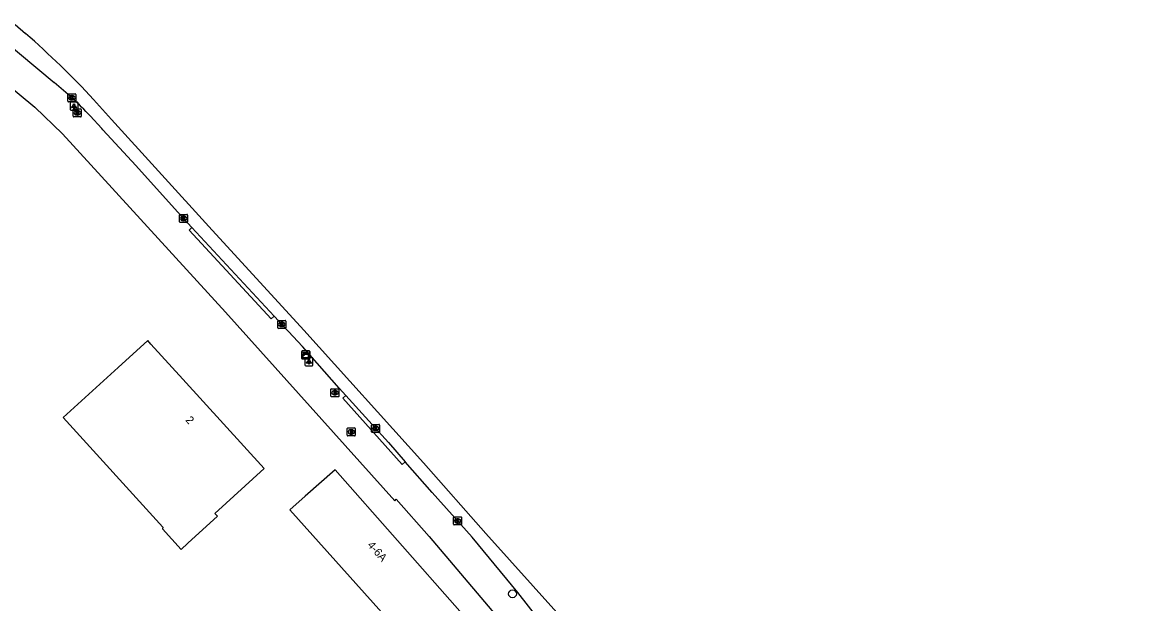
# Model space of a CAD drawing. Extents: x 161354 to 161876, y 382161 to 382804.
# Drawn here: x 161566.5 to 161706, y 382658.6 to 382731.2 of the extents above; entities that cross this region are included whole.
import ezdxf

# ---------------------------------------------------------------- set-up
doc = ezdxf.new("R2010")
doc.units = 0
for name, color, linetype in [('IMGEO_Boom', 7, 'Continuous'), ('IMGEO_Brandkraan', 7, 'Continuous'), ('IMGEO_Fietspad_gesloten', 7, 'Continuous'), ('IMGEO_Kast', 7, 'Continuous'), ('IMGEO_Kolk', 7, 'Continuous'), ('IMGEO_Lichtpunt', 7, 'Continuous'), ('IMGEO_Pand', 7, 'Continuous'), ('IMGEO_Pand_nummerreeks', 7, 'Continuous'), ('IMGEO_Rijbaan_lokaal_gesloten', 7, 'Continuous'), ('IMGEO_Rioolput', 7, 'Continuous'), ('IMGEO_Voetpad_open', 7, 'Continuous')]:
    doc.layers.add(name, color=color, linetype=linetype)

msp = doc.modelspace()

# ---------------------------------------------------------------- linework, layer by layer
at = {"layer": 'IMGEO_Boom'}
msp.add_circle((161627.74, 382659.79), 0.489, dxfattribs=at)
at = {"layer": 'IMGEO_Brandkraan'}
for p, q in [((161607.09, 382679.6), (161607.09, 382680.45)), ((161607.16, 382680.52), (161608.01, 382680.52)), ((161608.01, 382679.52), (161607.16, 382679.52)), ((161607.6, 382679.74), (161607.57, 382679.74)), ((161607.58, 382680.3), (161607.6, 382680.3)), ((161608.09, 382680.45), (161608.09, 382679.6))]:
    msp.add_line(p, q, dxfattribs=at)
for points in [[(161607.09, 382679.6), (161607.09, 382680.45)], [(161607.16, 382680.52), (161608.01, 382680.52)], [(161608.01, 382679.52), (161607.16, 382679.52)], [(161607.43, 382680.22), (161607.43, 382679.82), (161607.65, 382679.82)], [(161607.67, 382680.22), (161607.43, 382680.22)], [(161607.61, 382680.14), (161607.56, 382680.14), (161607.56, 382680.07)], [(161607.56, 382680.07), (161607.61, 382680.07)], [(161607.62, 382679.99), (161607.56, 382679.99), (161607.56, 382679.91)], [(161607.56, 382679.91), (161607.62, 382679.91)], [(161608.09, 382680.45), (161608.09, 382679.6)]]:
    msp.add_lwpolyline(points, dxfattribs=at)
for centre, radius, start, end in [((161607.16, 382680.45), 0.0765, 91.552, 178.448), ((161607.16, 382680.45), 0.0765, 91.552, 178.448), ((161607.16, 382679.6), 0.0765, 181.552, 268.448), ((161607.16, 382679.6), 0.0765, 181.552, 268.448), ((161607.61, 382680.1), 0.0379, 267.8285, 90.9355), ((161607.62, 382679.95), 0.0404, 269.8759, 90.5077), ((161607.65, 382680.07), 0.251, 268.6676, 293.5347), ((161607.67, 382680.08), 0.145, 59.4692, 91.5367), ((161607.7, 382680.13), 0.0922, 285.5137, 58.1501), ((161607.7, 382679.93), 0.105, 301.3115, 78.989), ((161608.01, 382680.45), 0.0765, 1.552, 88.448), ((161608.01, 382680.45), 0.0765, 1.552, 88.448), ((161608.01, 382679.6), 0.0765, 271.552, 358.448), ((161608.01, 382679.6), 0.0765, 271.552, 358.448)]:
    msp.add_arc(centre, radius, start, end, dxfattribs=at)
for centre, major_axis, ratio, start_param, end_param in [((161607.57, 382680.02), (-0.387, 0.002), 0.722429, 4.712389, 7.853982), ((161607.6, 382680.02), (-0.39, 0.002), 0.717154, 1.570796, 4.712389)]:
    msp.add_ellipse(centre, major_axis=major_axis, ratio=ratio, start_param=start_param, end_param=end_param, dxfattribs=at)
at = {"layer": 'IMGEO_Fietspad_gesloten'}
for points in [[(161570.46, 382723.64), (161563.83, 382729.15)], [(161587.67, 382705.55), (161586.62, 382706.68), (161580.68, 382713.28), (161576.55, 382717.76), (161576.42, 382717.91), (161574.95, 382719.49)], [(161587.67, 382705.55), (161597.96, 382694.49)], [(161606.91, 382684.56), (161606.09, 382685.47), (161601.5, 382690.67), (161597.96, 382694.49)], [(161606.91, 382684.56), (161612.23, 382678.69), (161614.34, 382676.28)], [(161631.21, 382656.39), (161631.08, 382656.55), (161628.4, 382659.96), (161626.26, 382662.59), (161622.7, 382666.88), (161617.71, 382672.44), (161614.34, 382676.28)]]:
    msp.add_lwpolyline(points, dxfattribs=at)
msp.add_arc((161543.58, 382690.11), 42.98, 43.1263, 51.2866, dxfattribs=at)
at = {"layer": 'IMGEO_Kast'}
for p, q in [((161601.4, 382689.21), (161601.4, 382690.05)), ((161601.4, 382690.05), (161601.4, 382689.21)), ((161601.47, 382690.13), (161602.31, 382690.13)), ((161602.31, 382690.13), (161601.47, 382690.13)), ((161602.32, 382689.14), (161601.48, 382689.14)), ((161601.48, 382689.14), (161602.32, 382689.14)), ((161602.4, 382690.06), (161602.4, 382689.22)), ((161602.4, 382689.22), (161602.4, 382690.06))]:
    msp.add_line(p, q, dxfattribs=at)
for points in [[(161601.59, 382689.93), (161602.19, 382689.93), (161602.19, 382689.84), (161601.59, 382689.84), (161601.59, 382689.93)], [(161601.59, 382689.75), (161602.19, 382689.75), (161602.19, 382689.26), (161601.59, 382689.26), (161601.59, 382689.75)]]:
    msp.add_lwpolyline(points, dxfattribs=at)
msp.add_circle((161601.68, 382689.6), 0.0377, dxfattribs=at)
for centre, start, end in [((161601.48, 382690.06), 92.4484, 184.2845), ((161601.48, 382690.06), 92.4484, 184.2845), ((161601.48, 382689.21), 182.4484, 274.2845), ((161601.48, 382689.21), 182.4484, 274.2845), ((161602.32, 382690.06), 2.4484, 94.2845), ((161602.32, 382690.06), 2.4484, 94.2845), ((161602.32, 382689.21), 272.4484, 4.2845), ((161602.32, 382689.21), 272.4484, 4.2845)]:
    msp.add_arc(centre, 0.0779, start, end, dxfattribs=at)
at = {"layer": 'IMGEO_Kolk'}
for p, q in [((161572.17, 382721.32), (161572.17, 382722.17)), ((161572.24, 382722.25), (161573.09, 382722.25)), ((161573.09, 382721.25), (161572.24, 382721.25)), ((161572.68, 382721.47), (161572.65, 382721.47)), ((161572.66, 382722.03), (161572.68, 382722.03)), ((161573.17, 382722.17), (161573.17, 382721.32)), ((161586.13, 382706.26), (161586.13, 382707.11)), ((161586.2, 382707.18), (161587.05, 382707.18)), ((161587.05, 382706.18), (161586.2, 382706.18)), ((161586.61, 382706.96), (161586.64, 382706.96)), ((161586.64, 382706.4), (161586.61, 382706.4)), ((161587.13, 382707.11), (161587.13, 382706.26)), ((161598.41, 382693.02), (161598.41, 382693.87)), ((161598.48, 382693.95), (161599.33, 382693.95)), ((161598.89, 382693.73), (161598.92, 382693.73)), ((161599.41, 382693.87), (161599.41, 382693.02)), ((161599.33, 382692.95), (161598.48, 382692.95)), ((161598.92, 382693.17), (161598.89, 382693.17)), ((161610.12, 382680.03), (161610.12, 382680.88)), ((161610.2, 382680.96), (161611.05, 382680.96)), ((161611.13, 382680.88), (161611.13, 382680.03)), ((161611.05, 382679.96), (161610.2, 382679.96)), ((161610.61, 382680.74), (161610.64, 382680.74)), ((161610.63, 382680.18), (161610.61, 382680.18)), ((161620.38, 382668.48), (161620.38, 382669.33)), ((161620.46, 382669.4), (161621.31, 382669.4)), ((161621.31, 382668.4), (161620.46, 382668.4)), ((161620.87, 382669.18), (161620.9, 382669.18)), ((161620.89, 382668.62), (161620.87, 382668.62)), ((161621.38, 382669.33), (161621.38, 382668.48))]:
    msp.add_line(p, q, dxfattribs=at)
for points in [[(161572.17, 382721.32), (161572.17, 382722.17)], [(161572.24, 382722.25), (161573.09, 382722.25)], [(161573.09, 382721.25), (161572.24, 382721.25)], [(161572.49, 382721.95), (161572.61, 382721.95), (161572.61, 382721.8), (161572.74, 382721.95), (161572.91, 382721.95), (161572.76, 382721.8), (161572.91, 382721.55), (161572.76, 382721.55), (161572.68, 382721.71), (161572.61, 382721.64), (161572.61, 382721.55), (161572.49, 382721.55), (161572.49, 382721.95)], [(161573.17, 382722.17), (161573.17, 382721.32)], [(161586.13, 382706.26), (161586.13, 382707.11)], [(161586.2, 382707.18), (161587.05, 382707.18)], [(161587.05, 382706.18), (161586.2, 382706.18)], [(161586.45, 382706.88), (161586.57, 382706.88), (161586.57, 382706.73), (161586.7, 382706.88), (161586.86, 382706.88), (161586.72, 382706.73), (161586.87, 382706.48), (161586.72, 382706.48), (161586.63, 382706.65), (161586.57, 382706.58), (161586.57, 382706.48), (161586.45, 382706.48), (161586.45, 382706.88)], [(161587.13, 382707.11), (161587.13, 382706.26)], [(161598.41, 382693.02), (161598.41, 382693.87)], [(161598.48, 382693.95), (161599.33, 382693.95)], [(161598.73, 382693.65), (161598.85, 382693.65), (161598.85, 382693.5), (161598.98, 382693.65), (161599.14, 382693.65), (161599, 382693.5), (161599.15, 382693.25), (161599, 382693.25), (161598.91, 382693.41), (161598.85, 382693.34), (161598.85, 382693.25), (161598.73, 382693.25), (161598.73, 382693.65)], [(161599.41, 382693.87), (161599.41, 382693.02)], [(161599.33, 382692.95), (161598.48, 382692.95)], [(161610.12, 382680.03), (161610.12, 382680.88)], [(161610.2, 382680.96), (161611.05, 382680.96)], [(161611.13, 382680.88), (161611.13, 382680.03)], [(161611.05, 382679.96), (161610.2, 382679.96)], [(161610.44, 382680.66), (161610.57, 382680.66), (161610.57, 382680.5), (161610.7, 382680.66), (161610.86, 382680.66), (161610.72, 382680.51), (161610.87, 382680.26), (161610.72, 382680.26), (161610.63, 382680.42), (161610.57, 382680.35), (161610.57, 382680.26), (161610.44, 382680.26), (161610.44, 382680.66)], [(161620.38, 382668.48), (161620.38, 382669.33)], [(161620.46, 382669.4), (161621.31, 382669.4)], [(161621.31, 382668.4), (161620.46, 382668.4)], [(161620.7, 382669.1), (161620.83, 382669.1), (161620.83, 382668.95), (161620.96, 382669.1), (161621.12, 382669.1), (161620.97, 382668.95), (161621.13, 382668.7), (161620.97, 382668.7), (161620.89, 382668.87), (161620.83, 382668.8), (161620.83, 382668.7), (161620.7, 382668.7), (161620.7, 382669.1)], [(161621.38, 382669.33), (161621.38, 382668.48)]]:
    msp.add_lwpolyline(points, dxfattribs=at)
for centre, start, end in [((161572.24, 382722.17), 91.552, 178.448), ((161572.24, 382722.17), 91.552, 178.448), ((161572.24, 382721.32), 181.552, 268.448), ((161572.24, 382721.32), 181.552, 268.448), ((161573.09, 382722.17), 1.552, 88.448), ((161573.09, 382722.17), 1.552, 88.448), ((161573.09, 382721.32), 271.552, 358.448), ((161573.09, 382721.32), 271.552, 358.448), ((161586.2, 382707.11), 91.552, 178.448), ((161586.2, 382707.11), 91.552, 178.448), ((161586.2, 382706.26), 181.552, 268.448), ((161586.2, 382706.26), 181.552, 268.448), ((161587.05, 382707.11), 1.552, 88.448), ((161587.05, 382707.11), 1.552, 88.448), ((161587.05, 382706.26), 271.552, 358.448), ((161587.05, 382706.26), 271.552, 358.448), ((161598.48, 382693.87), 91.552, 178.448), ((161598.48, 382693.87), 91.552, 178.448), ((161599.33, 382693.87), 1.552, 88.448), ((161599.33, 382693.87), 1.552, 88.448), ((161598.48, 382693.02), 181.552, 268.448), ((161598.48, 382693.02), 181.552, 268.448), ((161599.33, 382693.02), 271.552, 358.448), ((161599.33, 382693.02), 271.552, 358.448), ((161610.2, 382680.88), 91.552, 178.448), ((161610.2, 382680.88), 91.552, 178.448), ((161611.05, 382680.88), 1.552, 88.448), ((161611.05, 382680.88), 1.552, 88.448), ((161610.2, 382680.03), 181.552, 268.448), ((161610.2, 382680.03), 181.552, 268.448), ((161611.05, 382680.03), 271.552, 358.448), ((161611.05, 382680.03), 271.552, 358.448), ((161620.46, 382669.33), 91.552, 178.448), ((161620.46, 382669.33), 91.552, 178.448), ((161620.46, 382668.48), 181.552, 268.448), ((161620.46, 382668.48), 181.552, 268.448), ((161621.31, 382669.33), 1.552, 88.448), ((161621.31, 382669.33), 1.552, 88.448), ((161621.31, 382668.48), 271.552, 358.448), ((161621.31, 382668.48), 271.552, 358.448)]:
    msp.add_arc(centre, 0.0765, start, end, dxfattribs=at)
for centre, major_axis, ratio, start_param, end_param in [((161572.65, 382721.75), (-0.387, 0.002), 0.722429, 4.712389, 7.853982), ((161572.68, 382721.75), (-0.39, 0.002), 0.717154, 1.570796, 4.712389), ((161586.61, 382706.68), (-0.387, 0.002), 0.722429, 4.712389, 7.853982), ((161586.64, 382706.68), (-0.39, 0.002), 0.717154, 1.570796, 4.712389), ((161598.89, 382693.45), (-0.387, 0.002), 0.722429, 4.712389, 7.853982), ((161598.92, 382693.45), (-0.39, 0.002), 0.717154, 1.570796, 4.712389), ((161610.61, 382680.46), (-0.387, 0.002), 0.722429, 4.712389, 7.853982), ((161610.64, 382680.46), (-0.39, 0.002), 0.717154, 1.570796, 4.712389), ((161620.87, 382668.9), (-0.387, 0.002), 0.722429, 4.712389, 7.853982), ((161620.89, 382668.9), (-0.39, 0.002), 0.717154, 1.570796, 4.712389)]:
    msp.add_ellipse(centre, major_axis=major_axis, ratio=ratio, start_param=start_param, end_param=end_param, dxfattribs=at)
at = {"layer": 'IMGEO_Lichtpunt'}
for p, q in [((161573.35, 382721.21), (161572.54, 382721.21)), ((161573.35, 382721.21), (161572.54, 382721.21)), ((161572.44, 382721.12), (161572.44, 382720.31)), ((161572.44, 382721.12), (161572.44, 382720.31)), ((161572.54, 382720.22), (161573.35, 382720.22)), ((161572.54, 382720.22), (161573.35, 382720.22)), ((161573.44, 382720.31), (161573.44, 382721.12)), ((161573.44, 382720.31), (161573.44, 382721.12)), ((161601.8, 382689.19), (161601.8, 382688.38)), ((161601.8, 382689.19), (161601.8, 382688.38)), ((161602.7, 382689.29), (161601.89, 382689.29)), ((161602.7, 382689.29), (161601.89, 382689.29)), ((161602.79, 382688.38), (161602.79, 382689.19)), ((161602.79, 382688.38), (161602.79, 382689.19)), ((161601.89, 382688.29), (161602.7, 382688.29)), ((161601.89, 382688.29), (161602.7, 382688.29))]:
    msp.add_line(p, q, dxfattribs=at)
for points in [[(161572.82, 382720.78), (161572.86, 382720.75), (161572.67, 382720.49), (161572.63, 382720.52), (161572.82, 382720.78)], [(161572.92, 382720.73), (161572.97, 382720.73), (161572.97, 382720.41), (161572.92, 382720.41), (161572.92, 382720.73)], [(161573.03, 382720.75), (161573.07, 382720.78), (161573.26, 382720.52), (161573.22, 382720.49), (161573.03, 382720.75)], [(161602.17, 382688.85), (161602.21, 382688.83), (161602.02, 382688.56), (161601.98, 382688.59), (161602.17, 382688.85)], [(161602.27, 382688.81), (161602.32, 382688.81), (161602.32, 382688.48), (161602.27, 382688.48), (161602.27, 382688.81)], [(161602.38, 382688.83), (161602.42, 382688.85), (161602.61, 382688.59), (161602.57, 382688.56), (161602.38, 382688.83)]]:
    msp.add_lwpolyline(points, dxfattribs=at)
for centre in [(161572.94, 382720.92), (161602.3, 382688.99)]:
    msp.add_circle(centre, 0.0994, dxfattribs=at)
for centre, start, end in [((161572.54, 382721.12), 90, 180), ((161572.54, 382721.12), 90, 180), ((161573.35, 382721.12), 0, 90), ((161573.35, 382721.12), 0, 90), ((161572.54, 382720.31), 180, 270), ((161572.54, 382720.31), 180, 270), ((161573.35, 382720.31), 270, 0), ((161573.35, 382720.31), 270, 360), ((161601.89, 382689.19), 90, 180), ((161601.89, 382689.19), 90, 180), ((161602.7, 382689.19), 0, 90), ((161602.7, 382689.19), 0, 90), ((161601.89, 382688.38), 180, 270), ((161601.89, 382688.38), 180, 270), ((161602.7, 382688.38), 270, 0), ((161602.7, 382688.38), 270, 360)]:
    msp.add_arc(centre, 0.0946, start, end, dxfattribs=at)
at = {"layer": 'IMGEO_Pand'}
for points in [[(161587.17, 382666.11), (161590.86, 382669.48), (161590.53, 382669.84), (161596.7, 382675.46), (161586.54, 382686.62), (161582.55, 382691), (161582.15, 382691.45), (161578.45, 382688.08), (161571.58, 382681.82), (161584.05, 382668.13), (161583.98, 382667.91), (161586.32, 382665.34), (161587.17, 382666.11)], [(161608.6, 382646.59), (161611.37, 382642.43), (161621.26, 382649.02), (161617.61, 382654.49), (161621.16, 382657.62), (161605.59, 382675.28), (161601.84, 382671.98), (161599.92, 382670.28), (161613.9, 382654.66), (161606.56, 382649.65), (161608.6, 382646.59)]]:
    msp.add_lwpolyline(points, dxfattribs=at)
at = {"layer": 'IMGEO_Rijbaan_lokaal_gesloten'}
for points in [[(161565.59, 382730.91), (161566.88, 382729.79)], [(161575.38, 382721.55), (161577.62, 382719.05), (161589.77, 382705.69), (161601.67, 382692.72), (161616.61, 382676.14), (161624.39, 382667.35), (161636.24, 382654.18), (161636.58, 382653.81), (161653.9, 382634.56), (161673.99, 382613.71), (161706.01, 382577.79), (161705.64, 382575.65)]]:
    msp.add_lwpolyline(points, dxfattribs=at)
msp.add_arc((161490.37, 382642.4), 116.15, 42.9532, 48.7982, dxfattribs=at)
at = {"layer": 'IMGEO_Rioolput'}
for p, q in [((161572.84, 382719.45), (161572.84, 382720.3)), ((161572.91, 382720.38), (161573.77, 382720.38)), ((161573.33, 382720.16), (161573.35, 382720.16)), ((161573.84, 382720.3), (161573.84, 382719.45)), ((161573.77, 382719.38), (161572.91, 382719.38)), ((161573.35, 382719.6), (161573.33, 382719.6)), ((161605.05, 382684.5), (161605.05, 382685.35)), ((161605.13, 382685.42), (161605.98, 382685.42)), ((161605.54, 382685.2), (161605.56, 382685.2)), ((161606.05, 382685.35), (161606.05, 382684.5)), ((161605.98, 382684.42), (161605.13, 382684.42)), ((161605.56, 382684.64), (161605.54, 382684.64))]:
    msp.add_line(p, q, dxfattribs=at)
for points in [[(161572.84, 382719.45), (161572.84, 382720.3)], [(161572.91, 382720.38), (161573.77, 382720.38)], [(161573.43, 382720.07), (161573.18, 382720.08), (161573.18, 382719.68)], [(161573.18, 382719.68), (161573.3, 382719.68), (161573.3, 382719.84), (161573.31, 382719.84)], [(161573.36, 382720), (161573.3, 382720), (161573.3, 382719.91)], [(161573.3, 382719.91), (161573.35, 382719.91)], [(161573.84, 382720.3), (161573.84, 382719.45)], [(161573.77, 382719.38), (161572.91, 382719.38)], [(161573.36, 382719.81), (161573.43, 382719.68), (161573.57, 382719.68), (161573.5, 382719.8)], [(161605.05, 382684.5), (161605.05, 382685.35)], [(161605.13, 382685.42), (161605.98, 382685.42)], [(161605.64, 382685.12), (161605.39, 382685.12), (161605.39, 382684.72)], [(161605.57, 382685.04), (161605.51, 382685.04), (161605.51, 382684.96)], [(161605.51, 382684.96), (161605.56, 382684.96)], [(161606.05, 382685.35), (161606.05, 382684.5)], [(161605.98, 382684.42), (161605.13, 382684.42)], [(161605.39, 382684.72), (161605.51, 382684.72), (161605.51, 382684.89), (161605.52, 382684.89)], [(161605.57, 382684.86), (161605.64, 382684.72), (161605.78, 382684.72), (161605.72, 382684.85)]]:
    msp.add_lwpolyline(points, dxfattribs=at)
for centre, radius, start, end in [((161572.92, 382720.3), 0.0765, 91.552, 178.448), ((161572.92, 382720.3), 0.0765, 91.552, 178.448), ((161573.31, 382719.79), 0.0533, 26.0293, 88.6989), ((161573.34, 382720.1), 0.19, 274.7715, 282.9687), ((161573.36, 382719.9), 0.0964, 77.0061, 93.1865), ((161573.38, 382719.96), 0.0378, 276.6634, 79.6772), ((161573.43, 382719.97), 0.109, 350.3612, 89.416), ((161573.43, 382719.96), 0.112, 277.5842, 350.9817), ((161573.41, 382719.75), 0.108, 29.5134, 73.7905), ((161573.76, 382720.3), 0.0765, 1.552, 88.448), ((161573.76, 382720.3), 0.0765, 1.552, 88.448), ((161572.92, 382719.45), 0.0765, 181.552, 268.448), ((161572.92, 382719.45), 0.0765, 181.552, 268.448), ((161573.76, 382719.45), 0.0765, 271.552, 358.448), ((161573.76, 382719.45), 0.0765, 271.552, 358.448), ((161605.13, 382685.35), 0.0765, 91.552, 178.448), ((161605.13, 382685.35), 0.0765, 91.552, 178.448), ((161605.55, 382685.15), 0.19, 274.7715, 282.9687), ((161605.57, 382684.95), 0.0964, 77.0061, 93.1865), ((161605.59, 382685), 0.0378, 276.6634, 79.6772), ((161605.64, 382685.01), 0.109, 350.3612, 89.416), ((161605.64, 382685.01), 0.112, 277.5842, 350.9817), ((161605.98, 382685.35), 0.0765, 1.552, 88.448), ((161605.98, 382685.35), 0.0765, 1.552, 88.448), ((161605.13, 382684.5), 0.0765, 181.552, 268.448), ((161605.13, 382684.5), 0.0765, 181.552, 268.448), ((161605.52, 382684.83), 0.0533, 26.0293, 88.6989), ((161605.62, 382684.8), 0.108, 29.5134, 73.7905), ((161605.98, 382684.5), 0.0765, 271.552, 358.448), ((161605.98, 382684.5), 0.0765, 271.552, 358.448)]:
    msp.add_arc(centre, radius, start, end, dxfattribs=at)
for centre, major_axis, ratio, start_param, end_param in [((161573.33, 382719.88), (-0.387, 0.002), 0.722429, 4.712389, 7.853982), ((161573.35, 382719.88), (-0.39, 0.002), 0.717154, 1.570796, 4.712389), ((161605.54, 382684.92), (-0.387, 0.002), 0.722429, 4.712389, 7.853982), ((161605.56, 382684.92), (-0.39, 0.002), 0.717154, 1.570796, 4.712389)]:
    msp.add_ellipse(centre, major_axis=major_axis, ratio=ratio, start_param=start_param, end_param=end_param, dxfattribs=at)
at = {"layer": 'IMGEO_Voetpad_open'}
for points in [[(161555.24, 382731.18), (161568.03, 382720.57), (161571.49, 382717.27), (161591.86, 382694.99), (161613.02, 382671.42), (161613.19, 382671.62), (161617.32, 382666.94), (161628.15, 382654.16)], [(161597.96, 382694.49), (161597.59, 382694.15), (161587.31, 382705.21), (161587.67, 382705.55)], [(161614.34, 382676.28), (161613.97, 382675.94), (161606.54, 382684.23), (161606.91, 382684.56)]]:
    msp.add_lwpolyline(points, dxfattribs=at)

# ---------------------------------------------------------------- texts
at = {"layer": 'IMGEO_Pand_nummerreeks'}
for s, rotation, p in [('2', 312.3268, (161586.81, 382681.45)), ('4-6A', 311.4002, (161609.54, 382665.84))]:
    msp.add_text(s, height=1, rotation=rotation, dxfattribs=at).set_placement(p)

doc.saveas('drawing.dxf')
